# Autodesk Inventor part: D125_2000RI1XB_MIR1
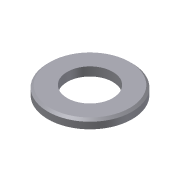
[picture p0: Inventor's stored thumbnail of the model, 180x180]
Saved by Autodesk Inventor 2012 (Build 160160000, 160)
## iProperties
Company: CAD-Verlag
Shininess: 64.0
Length Units: 11269
Angle Units: 11279
Time Units: 11290
Mass Units: 11283
Length Display Precision: 3
Angle Display Precision: 2
Compacted: True
Part Number: D125_2000RI1XB_MIR1
Document SubType Name: Modeling
Created: 2004-09
Material: Steel, Mild
Designer: Greiling
Manufacturer: Standard
Standards Organization: Custom
Density: 1 g/cm^3
Density: 0.0
Volumn: 0.0
Area: 0.0
PropertySet Name: Model Information
Control State: 0
Master: False
Checked Out: False
Author: Jürgen Kronas
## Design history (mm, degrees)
node "Unterlegscheibe DIN 125-B12" dims "d0" = 10, "d16" = 0
  node "WorkPlane1"
  node "WorkPlane3"
  node "MSC_PT1"
  node "MSC_PT2"
  node "WorkAxis1"
  node "MSC_A1"
  node "WorkPoint2"
  node "WorkPoint1"
node "Volumenkörper1"
node "Volumenkörpern"
node "Oberflächenkörpern"
tag "Bezeichnung2"
feature "Volumenkörper1::Unterlegscheibe DIN 125-B12" dims "d0" = 10, "d16" = 0
